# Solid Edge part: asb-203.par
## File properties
Last saved by: nakano
Revision: 76
Density: 2533.80685374888 kg/m^3
Accuracy: 0.990
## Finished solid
Body 1: solid body, 32 faces, 80 edges, 40 vertices.
  Faces by surface: cylinder 20, plane 12
  Edges by curve: circle 40, line 40
Bounding box of the edges (mm): 24.613 x 85.319 x 66.675, from (0, 0, -66.675) to (24.6126, 85.3186, 0).
Cylindrical faces by radius (mm): R0.254 x4, R1.1938 x8, R1.5875 x4, R4.0005 x2, R12.3063 x2
Planar faces by outward normal: +x 1, +y 1, +z 2, -x 1, -y 1, -z 2, oblique 4
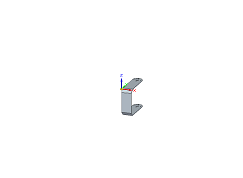
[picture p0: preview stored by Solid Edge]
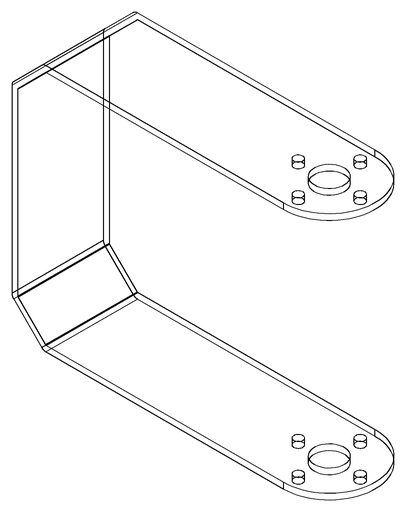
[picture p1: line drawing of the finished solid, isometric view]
